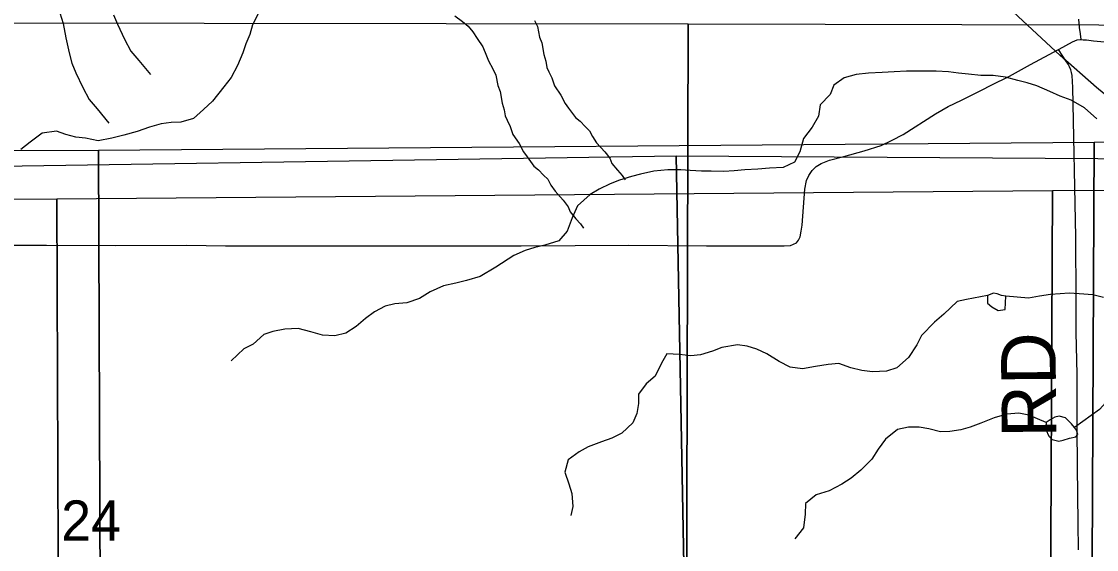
# Model space of a CAD drawing. Extents: x -21.1 to 50.3, y -4.9 to 22.1.
# Drawn here: x 4.771 to 5.889, y 19.604 to 20.154 of the extents above; entities that cross this region are included whole.
import ezdxf

# ---------------------------------------------------------------- set-up
doc = ezdxf.new("R2010")
doc.units = 0
for name, color, linetype in [('GM_X_County_Road', 7, 'Continuous'), ('GM_X_Minor_Lake', 7, 'Continuous'), ('GM_X_Minor_River', 7, 'Continuous'), ('GM_X_Rail_Line', 7, 'Continuous'), ('GM_X_Section', 7, 'Continuous'), ('GM_X_Section_Text', 7, 'Continuous'), ('GM_X_Township_Road', 7, 'Continuous'), ('GM_X_Township_Road_Text', 7, 'Continuous')]:
    doc.layers.add(name, color=color, linetype=linetype)

msp = doc.modelspace()

# ---------------------------------------------------------------- linework, layer by layer
at = {"layer": 'GM_X_County_Road'}
for points in [[(5.8732, 20.1351), (5.8724, 20.1409), (5.8714, 20.1475), (5.8706, 20.1564)], [(5.8494, 20.1247), (5.8503, 20.1252), (5.8639, 20.1326), (5.869, 20.1346), (5.8719, 20.1352), (5.8732, 20.1351)], [(5.8732, 20.1351), (5.8752, 20.1349), (5.8788, 20.1348), (5.8858, 20.1338), (5.9347, 20.1291)], [(4.7194, 19.9211), (4.7971, 19.9211), (4.8685, 19.9209), (4.9431, 19.921), (4.9834, 19.9205), (5.0206, 19.9203), (5.0921, 19.9204), (5.1821, 19.9205), (5.2256, 19.9204), (5.2909, 19.9203), (5.3468, 19.9206), (5.4027, 19.921), (5.4835, 19.9205), (5.5644, 19.9205), (5.5707, 19.9208), (5.5739, 19.922), (5.577, 19.9235), (5.5793, 19.9263), (5.5808, 19.9297), (5.5821, 19.9355), (5.583, 19.942), (5.5842, 19.9607), (5.5857, 19.9793), (5.5876, 19.9882), (5.59, 19.9937), (5.5933, 19.9987), (5.5977, 20.0028), (5.6028, 20.0061), (5.6113, 20.0095), (5.6263, 20.0134), (5.6473, 20.0191), (5.665, 20.0248), (5.6766, 20.0302), (5.6881, 20.0364), (5.7215, 20.0577), (5.7349, 20.0653), (5.7488, 20.0721), (5.7695, 20.0823), (5.7796, 20.0875), (5.7985, 20.0971), (5.8203, 20.109), (5.8494, 20.1247)]]:
    msp.add_lwpolyline(points, dxfattribs=at)
at = {"layer": 'GM_X_Minor_Lake'}
for points in [[(5.7947, 19.868), (5.7901, 19.8687), (5.7859, 19.8706), (5.7818, 19.871), (5.7757, 19.8687), (5.7757, 19.8608), (5.7802, 19.857), (5.7867, 19.8532), (5.7939, 19.854)], [(5.7939, 19.854), (5.7947, 19.868)], [(5.8681, 19.7284), (5.8662, 19.7315), (5.8632, 19.7352), (5.8568, 19.7413), (5.8503, 19.7432), (5.8458, 19.7421), (5.8408, 19.7394), (5.8367, 19.7364), (5.8363, 19.7292), (5.8393, 19.7224), (5.8431, 19.7189), (5.8499, 19.717), (5.8545, 19.7182), (5.8609, 19.7201)], [(5.8609, 19.7201), (5.8677, 19.7216), (5.8696, 19.724), (5.8681, 19.7284)]]:
    msp.add_lwpolyline(points, dxfattribs=at)
at = {"layer": 'GM_X_Minor_River'}
for points in [[(5.0192, 20.1653), (5.0116, 20.1505), (5.0086, 20.1402), (5.0044, 20.1307), (5.0013, 20.1213), (4.996, 20.108), (4.9892, 20.0955), (4.9816, 20.086), (4.9698, 20.0708), (4.9604, 20.0621), (4.9501, 20.053), (4.9369, 20.0492), (4.927, 20.0488), (4.9164, 20.0473), (4.9042, 20.0439), (4.8914, 20.0393), (4.8777, 20.0355), (4.8652, 20.0325), (4.8508, 20.0298), (4.8379, 20.0325), (4.8277, 20.0336), (4.8174, 20.0363), (4.8076, 20.0397), (4.7928, 20.0378)], [(4.8111, 20.163), (4.8147, 20.1516), (4.8175, 20.1368), (4.8207, 20.1213), (4.8235, 20.1103), (4.8278, 20.1005), (4.8351, 20.0851), (4.8417, 20.0726), (4.8498, 20.0628), (4.8621, 20.0482)], [(4.8668, 20.1609), (4.871, 20.151), (4.8784, 20.1356), (4.885, 20.1231), (4.8931, 20.1133), (4.9054, 20.0987)], [(5.2218, 20.1597), (5.2298, 20.1537), (5.2356, 20.1488), (5.2405, 20.1431), (5.2452, 20.1363), (5.2509, 20.1276), (5.2548, 20.1181), (5.2567, 20.1128), (5.2613, 20.1045)], [(5.3046, 20.155), (5.3077, 20.1486), (5.31, 20.1376), (5.3124, 20.1315), (5.3143, 20.1194), (5.3163, 20.1125), (5.3174, 20.1061), (5.3194, 20.1015), (5.3228, 20.0951), (5.3255, 20.0868), (5.3321, 20.0773), (5.3367, 20.0686), (5.3401, 20.0637), (5.3474, 20.0538), (5.352, 20.05), (5.3574, 20.0444), (5.362, 20.0402), (5.365, 20.0342), (5.3693, 20.0277), (5.3777, 20.0183), (5.3831, 20.0115), (5.385, 20.0062), (5.3911, 19.999), (5.3957, 19.9937), (5.3988, 19.9891)], [(5.2613, 20.1045), (5.2644, 20.0981), (5.2667, 20.0871), (5.2691, 20.081), (5.271, 20.0688), (5.273, 20.062), (5.2742, 20.0556), (5.2761, 20.051), (5.2795, 20.0446), (5.2823, 20.0362), (5.2888, 20.0268), (5.2934, 20.0181), (5.2969, 20.0131), (5.3041, 20.0033), (5.3087, 19.9995), (5.3141, 19.9939), (5.3187, 19.9897), (5.3218, 19.9836), (5.326, 19.9772), (5.3344, 19.9678), (5.3398, 19.961), (5.3417, 19.9556), (5.3478, 19.9485), (5.3524, 19.9432), (5.3555, 19.9386)], [(5.8895, 20.0527), (5.8766, 20.0641), (5.8626, 20.072), (5.8512, 20.0762), (5.8406, 20.0811), (5.827, 20.0868), (5.8171, 20.0899), (5.8073, 20.0925), (5.7944, 20.0959), (5.7815, 20.0978), (5.7686, 20.0978), (5.7561, 20.099), (5.7455, 20.1001), (5.7353, 20.1016), (5.7224, 20.102), (5.6913, 20.102), (5.6788, 20.1016), (5.6663, 20.1008), (5.6519, 20.1001), (5.6393, 20.0986), (5.6265, 20.0951), (5.6158, 20.0876), (5.612, 20.0777), (5.6018, 20.0671), (5.5999, 20.0553), (5.5934, 20.0439), (5.5843, 20.0322), (5.5805, 20.0182), (5.5749, 20.0075), (5.5631, 20.0018), (5.5491, 20.0011), (5.5369, 20.0003), (5.5233, 19.9996)], [(4.7928, 20.0378), (4.7803, 20.0283), (4.7704, 20.0207)], [(5.5233, 19.9996), (5.5123, 19.9984), (5.5017, 19.9977), (5.4884, 19.998), (5.4782, 19.998), (5.4664, 19.9988), (5.4569, 19.9996), (5.4433, 19.9996), (5.4289, 19.998), (5.4149, 19.995), (5.4054, 19.9927), (5.3929, 19.9886), (5.3834, 19.9848), (5.372, 19.9794), (5.3625, 19.9738), (5.3493, 19.962), (5.344, 19.9495), (5.3386, 19.9355), (5.3299, 19.9256), (5.3155, 19.921), (5.3049, 19.9188), (5.295, 19.9157), (5.2833, 19.9104), (5.2643, 19.8983), (5.248, 19.8884), (5.234, 19.8842), (5.223, 19.8816), (5.2101, 19.8786), (5.1961, 19.8725), (5.1851, 19.8657), (5.1718, 19.8611), (5.1593, 19.86), (5.1494, 19.8577), (5.1384, 19.8516), (5.1289, 19.8448), (5.1191, 19.8364), (5.1085, 19.8296), (5.0971, 19.8266), (5.0842, 19.8273), (5.0721, 19.8308), (5.0588, 19.8345), (5.0452, 19.8338), (5.0326, 19.8311), (5.0232, 19.8281), (5.0122, 19.8179), (5.0023, 19.8133), (4.9894, 19.8008)], [(5.7757, 19.8687), (5.7537, 19.8646), (5.7442, 19.8623), (5.7302, 19.8494), (5.7207, 19.8411), (5.7071, 19.827), (5.7021, 19.8172), (5.6934, 19.8043), (5.6813, 19.7933), (5.6706, 19.7898), (5.6562, 19.7891), (5.6449, 19.7906), (5.6335, 19.7936), (5.621, 19.7978), (5.61, 19.797), (5.5967, 19.7948), (5.5835, 19.7925), (5.5706, 19.794), (5.5592, 19.8001), (5.5463, 19.808), (5.5357, 19.813), (5.5258, 19.816), (5.5156, 19.8175), (5.4993, 19.8145), (5.4898, 19.8107), (5.4773, 19.8069), (5.4671, 19.8058), (5.4553, 19.8073), (5.4421, 19.808), (5.4367, 19.7982), (5.4303, 19.7849), (5.4208, 19.7769), (5.4128, 19.7659), (5.4128, 19.7564), (5.4109, 19.7458), (5.4068, 19.7363), (5.3954, 19.7253), (5.3851, 19.7204), (5.3742, 19.7166), (5.3605, 19.7113), (5.351, 19.706), (5.3396, 19.6977), (5.3362, 19.6848), (5.3404, 19.6726), (5.3434, 19.6628), (5.3445, 19.6491), (5.3426, 19.6396)], [(5.8962, 19.8665), (5.8853, 19.8695), (5.8709, 19.8706), (5.8606, 19.871), (5.8511, 19.8706), (5.8413, 19.8699), (5.8299, 19.868), (5.8182, 19.8661), (5.7947, 19.868)], [(6.0403, 19.8335), (6.0308, 19.8259), (6.0194, 19.8179), (6.0077, 19.8115), (5.9936, 19.8035), (5.9838, 19.7982), (5.9686, 19.7903), (5.9588, 19.7857), (5.9459, 19.7834), (5.9356, 19.7849), (5.9227, 19.7834), (5.911, 19.7743), (5.9019, 19.7607), (5.892, 19.75), (5.8662, 19.7315)], [(5.8367, 19.7364), (5.8185, 19.7443), (5.8082, 19.7462), (5.7957, 19.7451), (5.7825, 19.7413), (5.7688, 19.736), (5.7578, 19.7318), (5.748, 19.7288), (5.7366, 19.7273), (5.7267, 19.7269), (5.7146, 19.7299), (5.7047, 19.7318), (5.6934, 19.7318), (5.682, 19.7292), (5.6695, 19.7193), (5.6619, 19.7087), (5.6554, 19.6984), (5.6441, 19.6871), (5.6338, 19.6787), (5.6243, 19.6723), (5.6111, 19.6654), (5.5974, 19.6613), (5.5864, 19.6522), (5.586, 19.6412), (5.5845, 19.6268), (5.5754, 19.6154)]]:
    msp.add_lwpolyline(points, dxfattribs=at)
at = {"layer": 'GM_X_Rail_Line'}
msp.add_lwpolyline([(8.7124, 19.4385), (8.6321, 19.4947), (8.5569, 19.5639), (8.4846, 19.6311), (8.4351, 19.6802), (7.7677, 19.7799), (6.96, 19.8904), (6.0946, 20.0033), (6.0001, 20.0188), (5.9524, 20.041), (5.9167, 20.0621), (5.889, 20.0852), (5.8514, 20.1183), (5.4907, 20.4538), (5.1767, 20.7457), (5.0416, 20.8632), (4.985, 20.8984), (4.9816, 20.9)], dxfattribs=at)
at = {"layer": 'GM_X_Section'}
for points in [[(4.4577, 20.1527), (5.4645, 20.1514), (5.4617, 19.1492), (4.4602, 19.1433)], [(5.4645, 20.1514), (6.4606, 20.149), (6.4647, 19.1453), (5.4617, 19.1492)], [(5.8866, 20.0284), (6.8808, 20.0321), (6.8877, 19.0133), (6.8358, 19.0117), (5.8818, 19.0073)], [(3.824, 20.0181), (4.8512, 20.0198), (4.855, 19.0048), (4.8307, 19.0046), (3.8354, 19.0047)], [(4.8512, 20.0198), (5.8866, 20.0284), (5.8818, 19.0073), (5.8249, 19.0071), (4.855, 19.0048)], [(4.4995, 19.9996), (5.4518, 20.0139), (5.4711, 18.9972), (4.5067, 19.0018), (4.4996, 19.9379)], [(5.4518, 20.0139), (6.4936, 20.0075), (6.5046, 18.9888), (5.4711, 18.9972)], [(4.8079, 19.9693), (5.8433, 19.9779), (5.8385, 18.9568), (5.7817, 18.9566), (4.8117, 18.9543)], [(5.8433, 19.9779), (6.8375, 19.9816), (6.8444, 18.9628), (6.7925, 18.9612), (5.8385, 18.9568)], [(3.7807, 19.9676), (4.8079, 19.9693), (4.8117, 18.9543), (4.7875, 18.9541), (3.7921, 18.9542)]]:
    msp.add_lwpolyline(points, close=True, dxfattribs=at)
at = {"layer": 'GM_X_Township_Road'}
msp.add_lwpolyline([(5.8704, 19.6039), (5.87, 19.6318), (5.8693, 19.6908), (5.869, 19.7312), (5.8689, 19.7869), (5.868, 19.8303), (5.868, 19.8644), (5.8675, 19.9297), (5.8645, 20.085), (5.8637, 20.0976), (5.8632, 20.1008), (5.8622, 20.1037), (5.861, 20.1066), (5.8594, 20.1094), (5.8566, 20.1138), (5.854, 20.1178), (5.8494, 20.1247)], dxfattribs=at)

# ---------------------------------------------------------------- texts
at = {"layer": 'GM_X_Section_Text'}
msp.add_text('24', height=0.04186, rotation=0, dxfattribs=at).set_placement((4.8125, 19.6136))
at = {"layer": 'GM_X_Township_Road_Text'}
msp.add_text('RD', height=0.05682, rotation=90.4889, dxfattribs=at).set_placement((5.8473, 19.7209))

doc.saveas('drawing.dxf')
